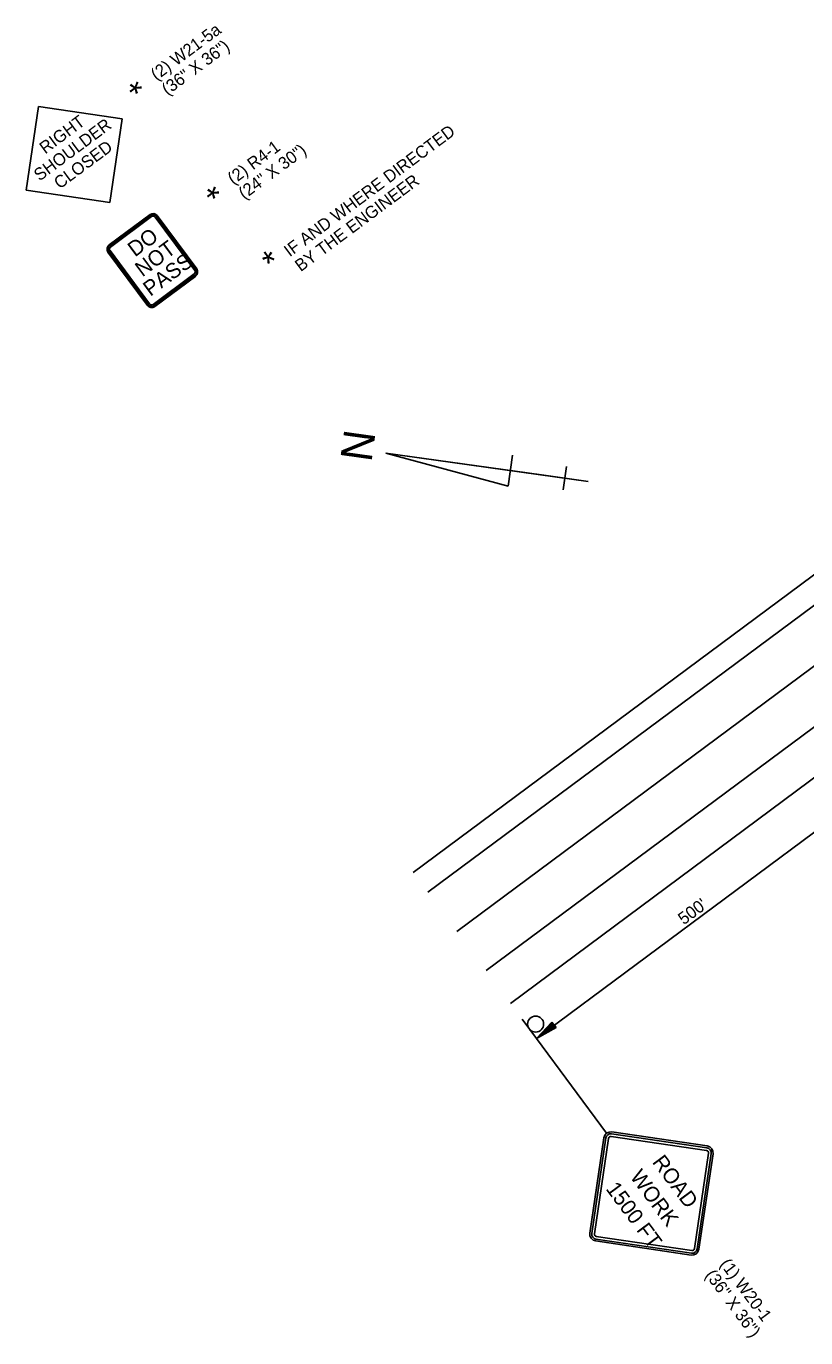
# Model space of a CAD drawing. Extents: x 998982 to 1000630, y 1875366 to 1876934.
# Drawn here: x 998982 to 999363, y 1875366 to 1876008 of the extents above; entities that cross this region are included whole.
import ezdxf

# ---------------------------------------------------------------- set-up
doc = ezdxf.new("R2010")
doc.units = 0
for name, color, linetype in [('P_TC_Signs_Permanent', 7, 'Continuous'), ('P_TC_Signs_Temporary', 7, 'Continuous'), ('R_Border Prem', 7, 'Continuous'), ('R_Draft', 7, 'Continuous'), ('STAMP', 7, 'Continuous')]:
    doc.layers.add(name, color=color, linetype=linetype)

msp = doc.modelspace()

# ---------------------------------------------------------------- linework, layer by layer
at = {"layer": 'P_TC_Signs_Permanent'}
for p, q in [((999042.28, 1875915.7), (999022.21, 1875900.79)), ((999042.58, 1875915.3), (999022.51, 1875900.39)), ((999043.02, 1875914.69), (999022.95, 1875899.79)), ((999064.15, 1875888.34), (999044.77, 1875914.44)), ((999064.75, 1875888.79), (999045.38, 1875914.88)), ((999065.15, 1875889.09), (999045.78, 1875915.18)), ((999021.69, 1875897.3), (999041.07, 1875871.2)), ((999022.09, 1875897.59), (999041.47, 1875871.5)), ((999022.69, 1875898.04), (999042.07, 1875871.95)), ((999043.82, 1875871.69), (999063.89, 1875886.59)), ((999044.27, 1875871.09), (999064.34, 1875885.99)), ((999044.56, 1875870.69), (999064.64, 1875885.59))]:
    msp.add_line(p, q, dxfattribs=at)
for centre, radius, start, end in [((999043.77, 1875913.69), 2.5, 36.59533, 126.59533), ((999043.77, 1875913.69), 2, 36.59533, 126.59533), ((999043.77, 1875913.69), 1.25, 36.59533, 126.59533), ((999023.7, 1875898.79), 2.5, 126.59533, 216.59533), ((999023.7, 1875898.79), 2, 126.59533, 216.59533), ((999023.7, 1875898.79), 1.25, 126.59533, 216.59533), ((999063.14, 1875887.6), 1.25, 306.59533, 36.59533), ((999063.14, 1875887.6), 2, 306.59533, 36.59533), ((999063.14, 1875887.6), 2.5, 306.59533, 36.59533), ((999043.07, 1875872.69), 2.5, 216.59533, 306.59533), ((999043.07, 1875872.69), 2, 216.59533, 306.59533), ((999043.07, 1875872.69), 1.25, 216.59533, 306.59533)]:
    msp.add_arc(centre, radius, start, end, dxfattribs=at)
at = {"layer": 'P_TC_Signs_Temporary'}
for p, q in [((999268.32, 1875465.63), (999315.06, 1875458.73)), ((999268.46, 1875466.56), (999315.2, 1875459.66)), ((999257.72, 1875416.97), (999264.63, 1875463.72)), ((999258.65, 1875416.84), (999265.55, 1875463.58)), ((999259.94, 1875416.65), (999266.85, 1875463.39)), ((999268.13, 1875464.34), (999314.87, 1875457.43)), ((999315.82, 1875456.15), (999308.91, 1875409.41)), ((999317.12, 1875455.96), (999310.21, 1875409.22)), ((999318.05, 1875455.82), (999311.14, 1875409.08)), ((999307.31, 1875406.24), (999260.56, 1875413.14)), ((999307.44, 1875407.16), (999260.7, 1875414.07)), ((999307.64, 1875408.46), (999260.89, 1875415.37))]:
    msp.add_line(p, q, dxfattribs=at)
for centre, radius, start, end in [((999267.96, 1875463.22), 3.38, 81.59533, 171.59533), ((999267.96, 1875463.22), 2.44, 81.59533, 171.59533), ((999267.96, 1875463.22), 1.12, 81.59533, 171.59533), ((999314.71, 1875456.32), 2.44, 351.59533, 81.59533), ((999314.71, 1875456.32), 3.37, 351.59533, 81.59533), ((999314.71, 1875456.32), 1.13, 351.59533, 81.59533), ((999261.06, 1875416.48), 3.38, 171.59533, 261.59533), ((999261.06, 1875416.48), 2.44, 171.59533, 261.59533), ((999261.06, 1875416.48), 1.13, 171.59533, 261.59533), ((999307.8, 1875409.57), 3.38, 261.59533, 351.59533), ((999307.8, 1875409.57), 2.44, 261.59533, 351.59533), ((999307.8, 1875409.57), 1.12, 261.59533, 351.59533)]:
    msp.add_arc(centre, radius, start, end, dxfattribs=at)
at = {"layer": 'R_Border Prem'}
for p, q in [((998987.69, 1875968.55), (998981.64, 1875927.64)), ((999028.6, 1875962.5), (998987.69, 1875968.55)), ((999028.6, 1875962.5), (999022.54, 1875921.61)), ((999022.54, 1875921.61), (998981.64, 1875927.64)), ((999256.88, 1875785.01), (999157.84, 1875798.86)), ((999157.84, 1875798.86), (999234.02, 1875788.21)), ((999157.84, 1875798.86), (999217.72, 1875782.72)), ((999217.72, 1875782.72), (999219.85, 1875797.96)), ((999244.65, 1875780.9), (999246.25, 1875792.32)), ((999256.88, 1875785.01), (999234.02, 1875788.21)), ((999245.45, 1875786.61), (999244.65, 1875780.9)), ((999256.88, 1875785.01), (999245.45, 1875786.61))]:
    msp.add_line(p, q, dxfattribs=at)
at = {"layer": 'R_Draft'}
for p, q in [((999192.61, 1875564.71), (999743.69, 1875973.9)), ((999171.2, 1875593.53), (999643.2, 1875944.01)), ((999178.34, 1875583.93), (999650.33, 1875934.4)), ((999206.88, 1875545.49), (999678.87, 1875895.96)), ((999218.77, 1875529.47), (999690.77, 1875879.94)), ((999392.1, 1875631.53), (999231.53, 1875512.3)), ((999239.16, 1875520.22), (999231.53, 1875512.3)), ((999241.15, 1875517.63), (999231.53, 1875512.3)), ((999239.33, 1875520), (999232.97, 1875513.41)), ((999240.98, 1875517.84), (999232.97, 1875513.41)), ((999239.5, 1875519.78), (999234.45, 1875514.54)), ((999240.81, 1875518.06), (999234.45, 1875514.54)), ((999239.66, 1875519.56), (999235.89, 1875515.65)), ((999240.65, 1875518.28), (999235.89, 1875515.65)), ((999239.83, 1875519.35), (999237.35, 1875516.77)), ((999240.48, 1875518.5), (999237.35, 1875516.77)), ((999240, 1875519.13), (999238.79, 1875517.88)), ((999240.31, 1875518.72), (999238.79, 1875517.88)), ((999241.15, 1875517.63), (999239.16, 1875520.22)), ((999231.53, 1875512.3), (999265.95, 1875465.93))]:
    msp.add_line(p, q, dxfattribs=at)
at = {"layer": 'STAMP'}
msp.add_line((999231.53, 1875512.3), (999224.53, 1875521.74), dxfattribs=at)
msp.add_circle((999231.17, 1875519.35), 3.92, dxfattribs=at)

# ---------------------------------------------------------------- texts
at = {"layer": 'P_TC_Signs_Permanent'}
for s, rotation, p in [('DO', 36.59533, (999034.9, 1875894.65)), ('NOT', 36.55497, (999038.53, 1875884.89)), ('PASS', 36.59533, (999042.45, 1875875.34))]:
    msp.add_text(s, height=7.5, rotation=rotation, dxfattribs=at).set_placement(p)
at = {"layer": 'P_TC_Signs_Temporary'}
for s, p in [(' ROAD ', (999286.32, 1875453.95)), ('WORK', (999277.08, 1875444.56)), ('1500 FT', (999265.25, 1875438.64))]:
    msp.add_text(s, height=7.5, rotation=306.59533, dxfattribs=at).set_placement(p)
at = {"layer": 'R_Border Prem'}
for s, height, rotation, p in [('(2) W21-5a', 6, 36.59533, (999045.44, 1875981.06)), ('(36" X 36")', 6, 36.59533, (999050.8, 1875973.84)), ('*', 12, 126.59533, (999044, 1875980.47)), ('SHOULDER', 6, 36.59577, (998988.19, 1875931.83)), ('RIGHT ', 6, 36.59577, (998990.95, 1875945.08)), ('IF AND WHERE DIRECTED ', 6, 36.59533, (999110.72, 1875894.69)), ('CLOSED', 6, 36.59577, (998998.04, 1875927.93)), ('(2) R4-1', 6, 36.59533, (999083.06, 1875930.09)), ('(24" X 30")', 6, 36.59533, (999088.43, 1875922.87)), ('BY THE ENGINEER', 6, 36.59533, (999116.09, 1875887.46)), ('*', 12, 126.59533, (999081.92, 1875929.09)), ('*', 12, 36.59533, (999102.93, 1875885.88)), ('N', 15.38, 82.03769, (999150.71, 1875794.17)), ("500'", 6, 36.59533, (999303.72, 1875567.68)), ('(1) W20-1', 6, 306.59533, (999321.18, 1875401.78)), ('(36" X 36")', 6, 306.59533, (999313.95, 1875396.41))]:
    msp.add_text(s, height=height, rotation=rotation, dxfattribs=at).set_placement(p)

doc.saveas('drawing.dxf')
